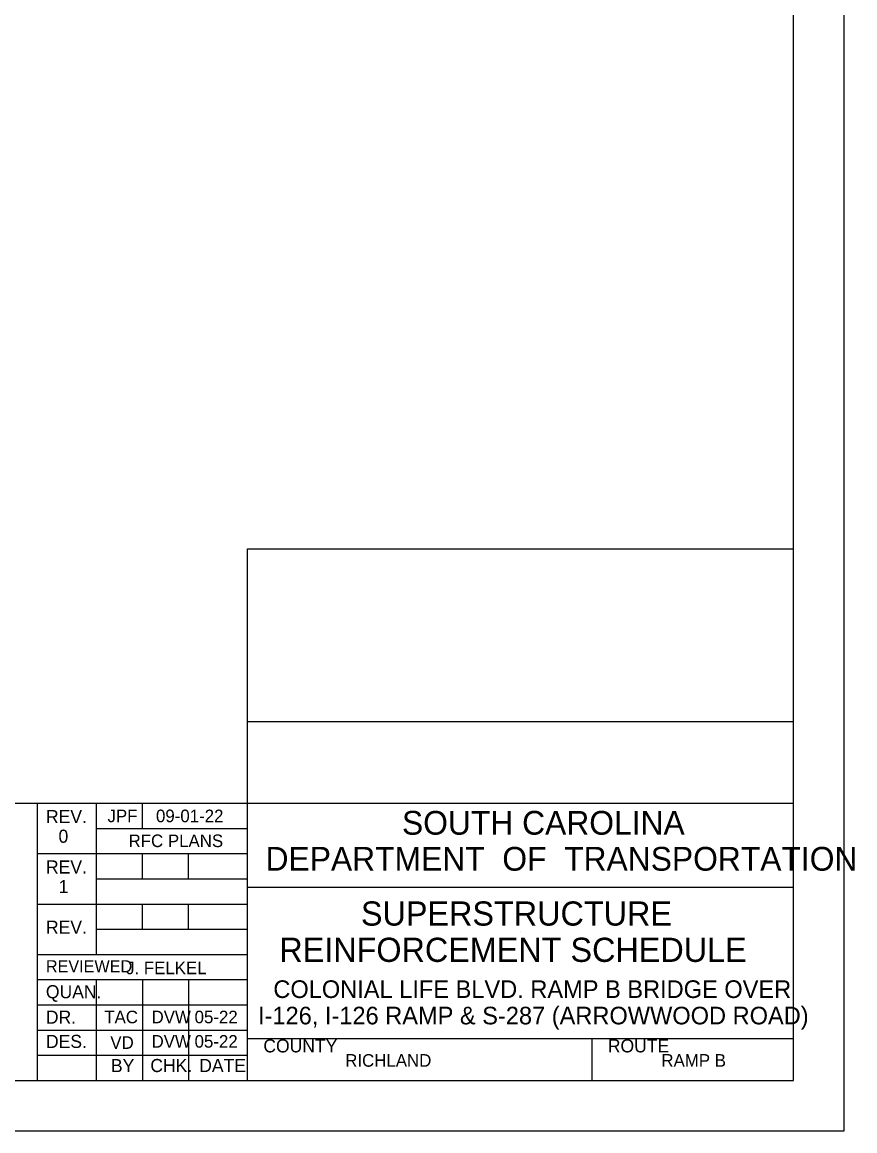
# Model space of a CAD drawing. Extents: x -125.5 to -89.4, y -5.1 to 16.9.
# Drawn here: x -97.69 to -89.43, y -5.07 to 5.93 of the extents above; entities that cross this region are included whole.
import ezdxf

# ---------------------------------------------------------------- set-up
doc = ezdxf.new("R2010")
doc.units = 0
for name, color, linetype in [('BR_BORDER LINES', 7, 'Continuous'), ('BR_TEXT', 7, 'Continuous'), ('Level 31', 7, 'Continuous')]:
    doc.layers.add(name, color=color, linetype=linetype)

msp = doc.modelspace()

# ---------------------------------------------------------------- linework, layer by layer
at = {"layer": 'BR_BORDER LINES'}
for p, q in [((-90.033, -4.566), (-90.033, 16.434)), ((-95.45, -4.566), (-95.45, 0.71)), ((-95.45, 0.71), (-90.033, 0.71)), ((-95.45, -1.004), (-90.033, -1.004)), ((-102.899, -1.816), (-97.534, -1.816)), ((-97.534, -4.566), (-97.534, -1.816)), ((-97.534, -1.816), (-90.033, -1.816)), ((-96.95, -1.816), (-96.95, -3.316)), ((-96.492, -2.066), (-96.492, -1.816)), ((-96.95, -2.066), (-95.45, -2.066)), ((-97.534, -2.316), (-95.45, -2.316)), ((-96.492, -2.566), (-96.492, -2.316)), ((-96.034, -2.566), (-96.034, -2.316)), ((-96.95, -2.566), (-95.45, -2.566)), ((-95.45, -2.649), (-95.45, -2.649)), ((-95.45, -2.649), (-90.033, -2.649)), ((-97.534, -2.816), (-95.45, -2.816)), ((-96.492, -3.066), (-96.492, -2.816)), ((-96.034, -3.066), (-96.034, -2.816)), ((-96.95, -3.066), (-95.45, -3.066)), ((-97.534, -3.316), (-95.45, -3.316)), ((-97.534, -3.566), (-95.45, -3.566)), ((-96.95, -3.566), (-96.95, -4.566)), ((-96.492, -3.566), (-96.492, -4.566)), ((-96.034, -3.566), (-96.034, -4.566)), ((-97.534, -3.816), (-95.45, -3.816)), ((-97.534, -4.066), (-95.45, -4.066)), ((-95.45, -4.149), (-90.033, -4.149)), ((-95.353, -4.149), (-90.033, -4.149)), ((-92.033, -4.566), (-92.033, -4.149)), ((-97.534, -4.316), (-95.45, -4.316)), ((-123.699, -4.566), (-90.033, -4.566))]:
    msp.add_line(p, q, dxfattribs=at)
at = {"layer": 'Level 31'}
msp.add_line((-92.742, -3.09), (-92.742, -3.09), dxfattribs=at)
msp.add_line((-92.742, -3.09), (-92.742, -3.09), dxfattribs=at)
msp.add_lwpolyline([(-125.533, -5.066), (-89.533, -5.066), (-89.533, 16.934), (-125.533, 16.934)], close=True, dxfattribs=at)

# ---------------------------------------------------------------- texts
at = {"layer": 'BR_TEXT'}
for s, height, p in [('REV.', 0.13, (-97.449, -2.013)), ('JPF', 0.125, (-96.839, -2.004)), ('09-01-22', 0.125, (-96.358, -2.004)), ('SOUTH CAROLINA', 0.23587, (-93.918, -2.128)), ('0', 0.13, (-97.325, -2.208)), ('RFC PLANS', 0.125, (-96.63, -2.251)), ('DEPARTMENT  OF  TRANSPORTATION', 0.23587, (-95.271, -2.485)), ('REV.', 0.13, (-97.449, -2.513)), ('1', 0.13, (-97.323, -2.708)), ('SUPERSTRUCTURE  ', 0.24, (-94.325, -3.03)), ('REV.', 0.13, (-97.449, -3.111)), ('REINFORCEMENT SCHEDULE', 0.24, (-95.135, -3.39)), ('REVIEWED', 0.12, (-97.45, -3.493)), ('J. FELKEL', 0.125, (-96.655, -3.512)), ('QUAN.', 0.13, (-97.45, -3.751)), ('COLONIAL LIFE BLVD. RAMP B BRIDGE OVER', 0.175, (-95.194, -3.748)), ('I-126, I-126 RAMP & S-287 (ARROWWOOD ROAD) ', 0.175, (-95.346, -4.01)), ('DR.', 0.13, (-97.45, -4.003)), ('TAC', 0.125, (-96.871, -3.999)), ('DVW', 0.125, (-96.402, -3.999)), ('05-22', 0.125, (-95.975, -3.999)), ('DES.', 0.13, (-97.449, -4.244)), ('VD', 0.125, (-96.811, -4.253)), ('DVW', 0.125, (-96.402, -4.241)), ('05-22', 0.125, (-95.975, -4.241)), ('COUNTY', 0.13, (-95.293, -4.288)), ('ROUTE', 0.13, (-91.876, -4.288)), ('BY', 0.13, (-96.805, -4.484)), ('CHK.', 0.13, (-96.414, -4.483)), ('DATE', 0.13, (-95.929, -4.483)), ('RICHLAND', 0.125, (-94.481, -4.43)), ('RAMP B', 0.125, (-91.345, -4.43))]:
    msp.add_text(s, height=height, dxfattribs=at).set_placement(p)

doc.saveas('drawing.dxf')
